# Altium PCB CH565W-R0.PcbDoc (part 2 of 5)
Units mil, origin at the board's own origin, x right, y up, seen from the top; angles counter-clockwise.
Board outline 3947.04 x 3947.04 mil, 4 copper layers (Top Layer, Layer 1, Layer 2, Bottom Layer), stack 23.756 mil thick; 204 components, 168 nets, 932 pads, 1005 vias.
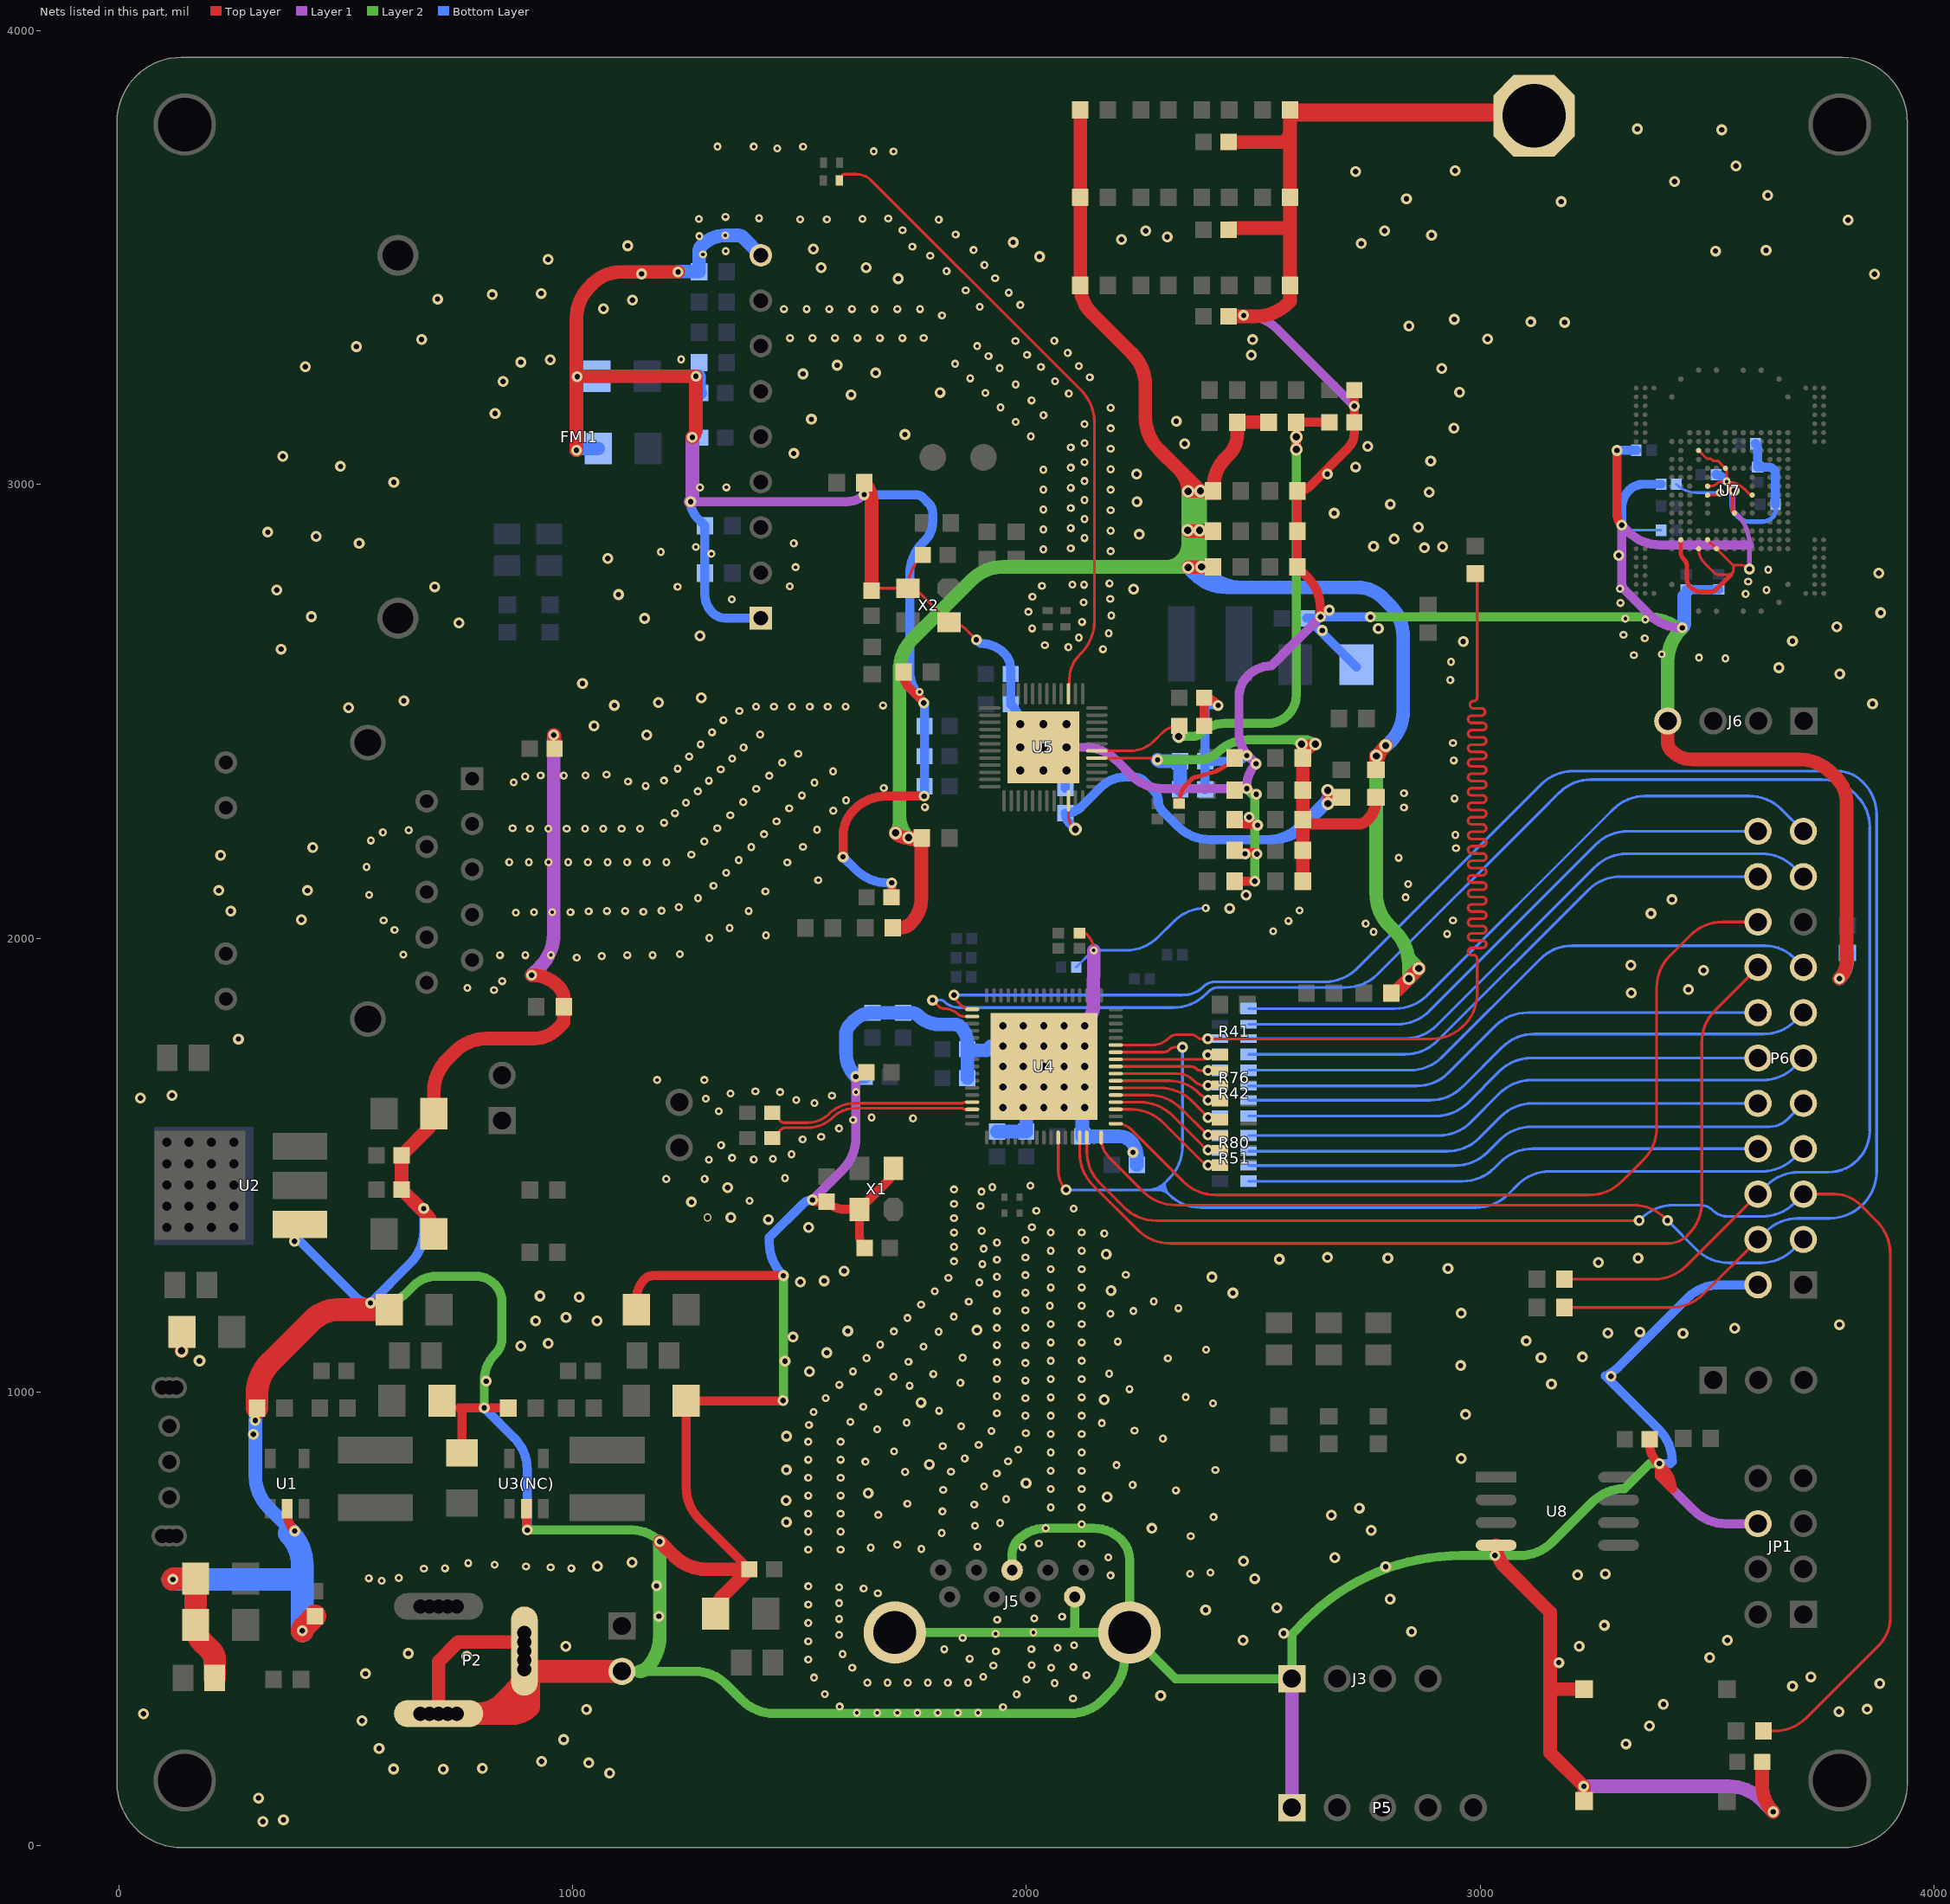
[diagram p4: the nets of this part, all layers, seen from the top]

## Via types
v1: diameter 17.72, hole 7.87, Top Layer to Bottom Layer, 556 vias
v2: diameter 24, hole 12, Top Layer to Bottom Layer, 366 vias
v3: diameter 28, hole 16, Top Layer to Bottom Layer, 63 vias
v4: diameter 17.72, hole 7.87, Top Layer to Bottom Layer, tented both sides, 8 vias
v5: diameter 24, hole 12, Top Layer to Bottom Layer, tented both sides, 5 vias
v6: diameter 26, hole 14, Top Layer to Bottom Layer, 2 vias
v7: diameter 19.68, hole 10, Top Layer to Bottom Layer, 1 vias
v8: diameter 20, hole 10, Top Layer to Bottom Layer, 1 vias
v9: diameter 28, hole 16, Top Layer to Bottom Layer, tented both sides, 1 vias
v10: diameter 32, hole 18, Top Layer to Bottom Layer, 1 vias
v11: diameter 17.72, hole 12, Top Layer to Bottom Layer, 1 vias

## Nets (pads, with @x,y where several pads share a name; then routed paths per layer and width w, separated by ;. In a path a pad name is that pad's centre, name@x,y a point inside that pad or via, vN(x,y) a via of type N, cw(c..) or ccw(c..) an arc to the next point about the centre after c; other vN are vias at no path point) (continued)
CMD_1: R41.6 R77.2 U4.29 | length 2954.6
  Top Layer w6: U4.29@2196.78,1764.37 2275.73,1764.37 ccw(c2275.73,1820.59) 2315.48,1780.83 ; 2315.5,1780.85 cw(c2331.46,1764.86) 2331.46,1787.45 2361.83,1787.45 cw(c2361.83,1765.31) 2377.49,1780.97 ccw(c2384.42,1787.9) 2384.42,1778.09 v2(2399.74,1778.09) 2893.6,1778.09 ccw(c2893.6,1878.09) 2993.6,1878.09 2993.6,1951.69 2993.6,1954.69 ccw(c2985.6,1954.69) 2985.6,1962.69 2981.6,1962.69 cw(c2981.6,1970.69) 2981.6,1978.69 3005.6,1978.69 ccw(c3005.6,1986.69) 3005.6,1994.69 2981.6,1994.69 cw(c2981.6,2002.69) 2981.6,2010.69 3005.6,2010.69 ccw(c3005.6,2018.69) 3005.6,2026.69 2981.6,2026.69 cw(c2981.6,2034.69) 2981.6,2042.69 3005.6,2042.69 ccw(c3005.6,2050.69) 3005.6,2058.69 2981.6,2058.69 cw(c2981.6,2066.69) 2981.6,2074.69 3005.6,2074.69 ccw(c3005.6,2082.69) 3005.6,2090.69 2981.6,2090.69 cw(c2981.6,2098.69) 2981.6,2106.69 3005.6,2106.69 ccw(c3005.6,2114.69) 3005.6,2122.69 2981.6,2122.69 cw(c2981.6,2130.69) 2981.6,2138.69 3005.6,2138.69 ccw(c3005.6,2146.69) 3005.6,2154.69 2981.6,2154.69 cw(c2981.6,2162.69) 2981.6,2170.69 3005.6,2170.69 ccw(c3005.6,2178.69) 3005.6,2186.69 2981.6,2186.69 cw(c2981.6,2194.69) 2981.6,2202.69 3005.6,2202.69 ccw(c3005.6,2210.69) 3005.6,2218.69 2981.6,2218.69 cw(c2981.6,2226.69) 2981.6,2234.69 3005.6,2234.69 ccw(c3005.6,2242.69) 3005.6,2250.69 2981.6,2250.69 cw(c2981.6,2258.69) 2981.6,2266.69 3005.6,2266.69 ccw(c3005.6,2274.69) 3005.6,2282.69 2981.6,2282.69 cw(c2981.6,2290.69) 2981.6,2298.69 3005.6,2298.69 ccw(c3005.6,2306.69) 3005.6,2314.69 2981.6,2314.69 cw(c2981.6,2322.69) 2981.6,2330.69 3005.6,2330.69 ccw(c3005.6,2338.69) 3005.6,2346.69 2981.6,2346.69 cw(c2981.6,2354.69) 2981.6,2362.69 3005.6,2362.69 ccw(c3005.6,2370.69) 3005.6,2378.69 2981.6,2378.69 cw(c2981.6,2386.69) 2981.6,2394.69 3005.6,2394.69 ccw(c3005.6,2402.69) 3005.6,2410.69 2981.6,2410.69 cw(c2981.6,2418.69) 2981.6,2426.69 3005.6,2426.69 ccw(c3005.6,2434.69) 3005.6,2442.69 2981.6,2442.69 cw(c2981.6,2450.69) 2981.6,2458.69 3005.6,2458.69 ccw(c3005.6,2466.69) 3005.6,2474.69 2981.6,2474.69 cw(c2981.6,2482.69) 2981.6,2490.69 3003,2490.69 ccw(c3003,2498.69) 3003,2506.69 2985.6,2506.69 cw(c2985.6,2514.69) 2985.6,2522.69 ccw(c2985.6,2530.69) 2993.6,2530.69 2993.6,2583.84 R77.2@2993.6,2803.67
  Bottom Layer w6: v2(2399.74,1778.09) cw(c2400.92,1776.92) 2400.92,1778.58 R41.6@2426.52,1778.58
CMD_2: R79.1 U7.R5 | length 130.2
  Top Layer w6: U7.R5@3501.47,2976.74 3515.72,2976.74 ccw(c3515.72,2995.22) v4(3528.79,2982.15)
  Bottom Layer w6: R79.1@3432.34,3000.83 ccw(c3477.44,3045.93) 3477.44,2982.15 v4(3528.79,2982.15)
DATA0: R41.5 R76.1 U4.27 | length 235.5
  Top Layer w6: U4.27@2196.78,1732.87 2390.04,1732.87 ccw(c2390.04,1742.61) v2(2399.78,1742.61) 2426.52,1742.61 R76.1@2426.52,1742.82
DATA1: R42.4 R76.2 U4.26 | length 205.7
  Top Layer w6: U4.26@2196.78,1717.12 2362.17,1717.12 cw(c2362.17,1699.04) 2374.96,1711.83 ccw(c2383.66,1720.52) 2383.66,1708.22 v2(2400.13,1708.22)
DATA2: R42.3 R76.3 U4.25 | length 210.8
  Top Layer w6: U4.25@2196.78,1701.37 2333.33,1701.37 cw(c2333.33,1653.71) 2367.03,1687.41 2367.21,1687.24 ccw(c2400.13,1720.16) v2@2400.13,1673.6
  other v2: 2400.13,1675.6
DATA3: R42.2 R76.4 U4.24 | length 241.4
  Top Layer w6: U4.24@2196.78,1685.63 2314.57,1685.63 cw(c2314.57,1592.62) 2380.34,1658.38 ccw(c2419.81,1697.85) 2419.81,1642.03 R76.4@2426.52,1642.03
  other v2: 2400.13,1642.97
DATA4: R42.1 R80.1 U4.23 | length 252.2
  Top Layer w6: U4.23@2196.78,1669.88 2294.3,1669.88 cw(c2294.3,1569.88) 2365.01,1640.59 2390.65,1614.95 ccw(c2426.52,1650.83) R80.1@2426.52,1600.1
  other v2: 2400.13,1604.35
DATA5: R51.4 R80.2 U4.22 | length 234.4
  Top Layer w6: U4.22@2196.78,1654.13 2269.88,1654.13 cw(c2269.88,1554.13) 2340.59,1624.84 v2@2399.07,1566.36
  other v2: 2400.13,1566.73
DATA6: R51.3 R80.3 U4.21 | length 267.4
  Top Layer w6: U4.21@2196.78,1638.38 2250.8,1638.38 cw(c2250.8,1538.38) 2321.51,1609.09 2387.57,1543.03 ccw(c2409.48,1564.94) 2409.48,1533.95 R80.3@2426.52,1533.95
  other v2: 2400.13,1533.1
DATA7: R51.2 R80.4 U4.20 | length 275.9
  Top Layer w6: U4.20@2196.78,1622.63 2230.76,1622.63 cw(c2230.76,1522.63) 2301.47,1593.34 2391.19,1503.62 ccw(c2399.07,1511.5) 2399.07,1500.36 ccw(c2401.61,1502.89) 2401.61,1499.31 R80.4@2426.52,1499.31
  other v2: 2400.13,1499.48
DP_CLK: P6.16 U4.14 | length 2123.8
  Top Layer w6.07: U4.14@2117.33,1560.34 2117.33,1526.1 ccw(c2217.33,1526.1) 2146.62,1455.39 2245.57,1356.45 ccw(c2316.28,1427.16) 2316.28,1327.16 3415.48,1327.16 ccw(c3415.48,1385.38) 3456.65,1344.21 3459.6,1347.16 ccw(c3389.29,1417.47) 3488.72,1417.47 3488.72,1770.43 cw(c3588.72,1770.43) 3518.01,1841.14 P6.16@3612.66,1935.79
DP_D0: P6.8 R51.8 | length 1144.2
  Bottom Layer w6.07: R51.8@2489.51,1464.19 2960.97,1464.19 ccw(c2960.97,1564.19) 3031.68,1493.48 3044.7,1506.5 cw(c3115.41,1435.79) 3115.41,1535.79 P6.8@3612.66,1535.79
DP_D1: P6.9 R51.7 | length 1268.8
  Bottom Layer w6.07: R51.7@2489.51,1498.84 2945.61,1498.84 ccw(c2945.61,1598.84) 3016.32,1528.13 3043.18,1554.99 cw(c3113.89,1484.28) 3113.89,1584.28 3637.83,1584.28 ccw(c3637.83,1640.61) 3677.65,1600.78 P6.9@3712.66,1635.79
DP_D2: P6.10 R51.6 | length 1158.2
  Bottom Layer w6.07: R51.6@2489.51,1530.33 2927.82,1530.33 ccw(c2927.82,1630.33) 2998.53,1559.62 3045.4,1606.5 cw(c3116.12,1535.79) 3116.12,1635.79 P6.10@3612.66,1635.79
DP_D3: P6.11 R51.5 | length 1281
  Bottom Layer w6.07: R51.5@2489.51,1564.98 2908.65,1564.98 ccw(c2908.65,1664.98) 2979.36,1594.27 3042.87,1657.78 cw(c3113.58,1587.06) 3113.58,1687.06 3622.52,1687.06 ccw(c3622.52,1787.06) 3693.23,1716.35 P6.11@3712.66,1735.79
DP_D4: P6.12 R42.8 | length 1167.5
  Bottom Layer w6.07: R42.8@2489.51,1608.03 2902.69,1608.03 ccw(c2902.69,1708.03) 2973.4,1637.32 3042.58,1706.5 cw(c3113.29,1635.79) 3113.29,1735.79 P6.12@3612.66,1735.79
DP_D5: P6.13 R42.7 | length 1290.4
  Bottom Layer w6.07: R42.7@2489.51,1642.68 2890.2,1642.68 ccw(c2890.2,1742.68) 2960.91,1671.96 3048.37,1759.43 cw(c3119.08,1688.71) 3119.08,1788.71 3625.78,1788.71 ccw(c3625.78,1884.82) 3693.74,1816.86 P6.13@3712.66,1835.79
DP_D6: P6.14 R42.6 | length 1181.5
  Bottom Layer w6.07: R42.6@2489.51,1674.17 2860.13,1674.17 ccw(c2860.13,1774.17) 2930.84,1703.46 3033.87,1806.5 cw(c3104.58,1735.79) 3104.58,1835.79 P6.14@3612.66,1835.79
DP_D7: P6.15 R42.5 | length 1344.2
  Bottom Layer w6.07: R42.5@2489.51,1708.82 2845.71,1708.82 ccw(c2845.71,1808.82) 2916.42,1738.11 3132.47,1954.16 cw(c3203.18,1883.45) 3203.18,1983.45 3628.41,1983.45 cw(c3628.41,1895.11) 3690.88,1957.57 P6.15@3712.66,1935.79
DP_D8: P6.20 R41.4 | length 1276.9
  Bottom Layer w6.07: R41.4@2489.51,1743.93 2834.65,1743.93 ccw(c2834.65,1843.93) 2905.36,1773.22 3238.64,2106.5 cw(c3309.35,2035.79) 3309.35,2135.79 P6.20@3612.66,2135.79
DP_D9: P6.19 R41.3 | length 1400
  Bottom Layer w6.07: R41.3@2489.51,1778.58 2833.7,1778.58 ccw(c2833.7,1878.58) 2904.41,1807.87 3253.47,2156.93 cw(c3324.18,2086.22) 3324.18,2186.22 3620.81,2186.22 cw(c3620.81,2086.22) 3691.52,2156.93 P6.19@3712.66,2135.79
DP_D10: P6.22 R41.2 | length 1290.9
  Bottom Layer w6.07: R41.2@2489.51,1810.08 2817.37,1810.08 ccw(c2817.37,1910.08) 2888.08,1839.37 3255.21,2206.5 cw(c3325.92,2135.79) 3325.92,2235.79 P6.22@3612.66,2235.79
DP_D11: P6.21 R41.1 | length 1436.5
  Bottom Layer w6.07: R41.1@2489.51,1844.72 2812.59,1844.72 ccw(c2812.59,1944.72) 2883.3,1874.01 3282.19,2272.91 3293.33,2284.04 cw(c3364.04,2213.33) 3364.04,2313.33 3593.7,2313.33 cw(c3593.7,2213.33) 3664.41,2284.04 P6.21@3712.66,2235.79
DP_HREF: P6.5 R27.1 U4.15 | length 3176.3
  Top Layer w6.07: U4.15@2133.08,1560.34 2133.08,1529.93 ccw(c2233.08,1529.93) 2162.37,1459.21 2214.95,1406.63 ccw(c2285.66,1477.34) 2285.66,1377.34 v2(3350.77,1377.34) ; R27.1@3624.9,252.09 3648.7,252.09 ccw(c3648.7,352.09) 3719.41,281.37 3878.66,440.63 ccw(c3816.73,502.56) 3904.31,502.56 3904.31,1304.48 ccw(c3804.31,1304.48) 3875.02,1375.19 3837.65,1412.57 ccw(c3781.59,1356.5) 3781.59,1435.79 P6.5@3718.64,1435.79
  Bottom Layer w6.07: v2(3350.77,1377.34) 3355.64,1382.21 cw(c3426.35,1311.5) 3426.35,1411.5 3485.15,1411.5 cw(c3485.15,1372) 3513.08,1399.93 ccw(c3545.42,1432.27) 3545.42,1386.53 3621.99,1386.53 ccw(c3621.99,1486.53) 3692.7,1415.82 P6.5@3712.66,1435.79
DP_PWDN: P6.18 U4.18 | length 1936.4
  Top Layer w6.07: U4.18@2196.78,1591.14 2199.66,1591.14 cw(c2199.66,1546.52) 2231.21,1578.07 2346.1,1463.18 ccw(c2416.81,1533.9) 2416.81,1433.9 3241.27,1433.9 ccw(c3241.27,1533.9) 3311.99,1463.18 3360.01,1511.21 ccw(c3289.3,1581.92) 3389.3,1581.92 3389.3,1890.85 cw(c3489.3,1890.85) 3418.59,1961.56 3463.53,2006.5 cw(c3534.24,1935.79) 3534.24,2035.79 P6.18@3612.66,2035.79
DP_RESET: P6.7 U4.11 U4.28 | length 2382.8
  Top Layer w6: U4.11@2070.09,1560.34 2070.09,1486.96 ccw(c2129.33,1486.96) v2(2087.44,1445.06) ; U4.28@2196.78,1748.62 2301.85,1748.62 ccw(c2301.85,1767.37) 2315.11,1754.11 cw(c2328.37,1740.85) 2328.37,1759.6 v2(2343.86,1759.6)
  Bottom Layer w6: v2(2087.44,1445.06) 2268.26,1445.06 ; 2295.79,1446.3 2299.31,1449.83 ; 2303.99,1453.09 ccw(c2303.99,1449.66) 2301.57,1452.08 2299.31,1449.83 ; 2313.86,1435.28 ccw(c2384.57,1505.99) 2384.57,1405.99 2991.19,1405.99 ccw(c2991.19,1505.99) 3061.9,1435.28 3083.28,1456.66 cw(c3153.99,1385.95) 3153.99,1485.95 3621.4,1485.95 ccw(c3621.4,1585.95) 3692.11,1515.24 P6.7@3712.66,1535.79 ; v2(2343.86,1759.6) 2343.86,1540.73 cw(c2243.86,1540.73) 2314.57,1470.02 2304.72,1460.17 ; 2268.26,1445.06 ccw(c2268.26,1496.63) 2295.99,1453.15 ; 2268.26,1445.06 2290.24,1445.06 ; 2290.24,1445.06 cw(c2291.75,1445.06) 2290.68,1446.13 2296.85,1452.29 ; 2290.24,1445.06 cw(c2290.24,1411.67) 2313.85,1435.29 ; 2295.99,1453.15 ccw(c2268.26,1496.63) 2304.72,1460.17 ; 2295.99,1453.15 2296.85,1452.29 ; 2296.85,1452.29 2304.72,1460.17 ; 2296.85,1452.29 2299.31,1449.83 ; 2299.31,1449.83 2313.85,1435.29 ; 2304.72,1460.17 2304.72,1457.34 ccw(c2335.91,1457.34) 2313.85,1435.29
DP_SCL: P6.4 R65.1 U4.52 | length 3946.9
  Top Layer w6.07: v2@1834.14,1873.51 1853.32,1854.33 ccw(c1880.41,1881.43) U4.52@1880.41,1843.11 ; R65.1@3184.61,1185.93 3421.39,1185.93 ccw(c3421.39,1285.93) 3492.1,1215.22 P6.4@3612.66,1335.79
  Bottom Layer w6.07: v2(1840.14,1874.51) 2344.63,1874.51 ccw(c2344.63,1939.35) 2362.64,1877.06 ccw(c2344.63,1939.35) 2376.51,1882.88 ccw(c2344.63,1939.35) 2390.48,1893.5 cw(c2415.41,1868.57) 2415.41,1903.82 2657.99,1903.82 ccw(c2657.99,2003.82) 2728.7,1933.11 3090.62,2295.03 3134.64,2339.06 cw(c3205.35,2268.35) 3205.35,2368.35 3787.69,2368.35 cw(c3787.69,2291.49) 3842.04,2345.84 3844.77,2343.11 cw(c3774.06,2272.4) 3874.06,2272.4 3874.06,2228.03 3874.06,1486.1 cw(c3770.2,1486.1) 3770.2,1382.24 3700.54,1382.24 ccw(c3700.54,1282.24) 3629.83,1352.96 P6.4@3612.66,1335.79
DP_SDA: P6.6 R64.1 U4.53 | length 3909.3
  Top Layer w6.07: v2(1792.99,1863.44) 1806.45,1849.97 ccw(c1819.12,1862.64) 1819.12,1844.73 cw(c1819.12,1801.49) 1849.69,1832.07 ccw(c1861.05,1843.43) 1861.05,1827.36 U4.53@1880.41,1827.36 ; R64.1@3182.86,1248.07 3383.52,1248.07 ccw(c3383.52,1348.07) 3454.23,1277.36 P6.6@3612.66,1435.79
  Bottom Layer w6.07: v2(1792.99,1863.44) 1811.08,1863.44 cw(c1811.08,1852.38) 1818.89,1860.2 ccw(c1850.61,1891.92) 1850.61,1847.06 2324.48,1847.06 ccw(c2324.48,1947.06) 2395.19,1876.35 2400.98,1882.14 cw(c2423.81,1859.31) 2423.81,1891.6 2703.84,1891.6 ccw(c2703.84,1991.6) 2774.55,1920.88 3132.01,2278.35 3174.22,2320.55 cw(c3244.93,2249.84) 3244.93,2349.84 3753.73,2349.84 cw(c3753.73,2249.84) 3824.44,2320.55 3829.84,2315.15 cw(c3759.13,2244.44) 3859.13,2244.44 3859.13,2207.64 3859.13,1575.61 cw(c3767.56,1575.61) 3767.56,1484.05 3702.34,1484.05 ccw(c3702.34,1384.05) 3631.63,1454.76 P6.6@3612.66,1435.79
DP_SYNC: P6.3 U4.17 | length 1679.2
  Top Layer w6.07: U4.17@2164.58,1560.34 ccw(c2227.67,1560.34) 2183.06,1515.73 2257.9,1440.89 ccw(c2328.61,1511.6) 2328.61,1411.6 3337.44,1411.6 cw(c3337.44,1311.6) 3408.15,1382.31 v2(3413.12,1377.34)
  Bottom Layer w6.07: v2(3413.12,1377.34) 3476.94,1313.52 ccw(c3547.65,1384.23) 3547.65,1284.23 3619.68,1284.23 ccw(c3619.68,1384.23) 3690.39,1313.52 P6.3@3712.66,1335.79
DVDD10: C52.2 R56.2 U5.22 | length 1201.1
  Top Layer w6: U5.22@2092.35,2302.68 2092.35,2272.72 ccw(c2138.17,2272.72) v3@2105.77,2240.32
  Top Layer w20: v3(2663.95,2325.72) 2663.95,2297.9 ccw(c2665.54,2297.9) v3(2664.42,2296.78) ; 2665.42,2310.78 2665.59,2310.61 R56.2@2694.06,2310.61
  Bottom Layer w20: v3(2107.77,2240.32) 2094.9,2253.2 cw(c2117.29,2275.59) C52.2@2085.63,2275.59 ccw(c2085.63,2327.11) 2122.06,2290.68 2164.91,2333.53 cw(c2217.16,2281.29) 2217.16,2355.17 2237.13,2355.17 cw(c2237.13,2322.58) 2260.18,2345.63 2282.04,2323.77 cw(c2263.77,2305.51) 2289.6,2305.51 ccw(c2325.58,2305.51) 2300.12,2280.08 2333.6,2246.61 ccw(c2404.31,2317.32) 2404.31,2217.32 2530.53,2217.32 ; 2530.53,2217.32 ccw(c2530.53,2317.32) 2601.24,2246.61 ; 2530.53,2217.32 ccw(c2530.53,2317.32) 2601.24,2246.61 ; 2530.53,2217.32 2543.53,2217.32 ccw(c2543.53,2317.32) 2614.24,2246.61 v3(2664.42,2296.78) ; 2601.24,2246.61 v3@2652.36,2297.72 ; v3@2652.36,2297.72 ccw(c2624.36,2325.72) v3@2663.95,2325.72 ; v3@2652.36,2297.72 v3@2663.95,2309.32 ; v3@2663.95,2309.32 v3(2663.95,2325.72) ; v3@2663.95,2309.32 2663.95,2297.9 ccw(c2665.54,2297.9) v3(2664.42,2296.78) ; v3@2663.95,2309.32 v3@2664.42,2309.78 ; v3@2663.95,2325.72 cw(c2662.83,2324.6) 2664.42,2324.6 v3@2664.42,2309.78 ; v3(2664.42,2296.78) v3@2664.42,2309.78
DVDD33: R17.2 R18.1 R28.1 R35.2 R37.1 R39.1 R43.2 R53.1 R57.1 R63.2 R66.1 R70.1 | length 5174
  Top Layer w30: R43.2@1705.4,2023.17 1721.35,2023.17 ccw(c1721.35,2057.54) 1745.65,2033.23 ccw(c1691.21,2087.68) 1768.21,2087.68 1768.21,2217.84 1749.32,2217.84 cw(c1749.32,2231.33) v3@1740.88,2220.81 ; v3(1711.3,2232) ccw(c1738.32,2259.02) 1738.32,2220.81 v3@1740.88,2220.81 ; v3(1739.79,2221.79) ccw(c1749.32,2231.33) v3@1740.88,2220.81 ; R53.1@1769.44,2220.81 v3@1740.88,2220.81 ; R66.1@2118.6,3823.63 R57.1@2118.6,3633.33 R70.1@2118.6,3439.1 ccw(c2205.54,3439.1) 2144.06,3377.62 2232.9,3288.78 cw(c2162.19,3218.07) 2262.19,3218.07 2262.19,3148.47 ccw(c2362.19,3148.47) 2291.48,3077.76 2336.65,3032.6 ; v3(2356.23,2817.13) cw(c2359.28,2814.07) 2359.28,2818.39 v3@2386.09,2818.39 ; v3@2356.23,2897.13 R37.1@2411.47,2897.13 ccw(c2406.24,2891.9) 2406.24,2899.3 v3(2381.77,2899.3) ; v3(2385.96,2818.51) v3@2386.09,2818.39 ; R28.1@2411.47,2818.39 v3@2386.09,2818.39 ; R18.1@2533.95,3137.48 R17.2@2464.53,3137.48 2464.53,3108.65 cw(c2405.98,3108.65) 2447.39,3067.26 2440.76,3060.63 ccw(c2511.47,2989.92) 2411.47,2989.92 R39.1@2411.47,2985.87 v3@2383.72,2985.87 ; R63.2@2770.33,2371.24 R63.2@2770.33,2372.53 ; v3(2771.11,2401.8) ccw(c2773.01,2399.9) 2770.33,2399.9 R63.2@2770.33,2372.53 ; v3(2791.87,2424.54) ccw(c2843.89,2372.53) R63.2@2770.33,2372.53 ; v3(2842.78,1910.56) 2816.38,1884.17 cw(c2804.2,1896.36) R35.2@2804.2,1879.13 ccw(c2804.2,1895.41) 2815.71,1883.9 v3(2865.11,1933.29) ; 2336.65,3032.6 cw(c2289.38,2985.32) v3(2356.23,2985.32) cw(c2357.55,2984.01) 2357.55,2985.87 v3@2383.38,2985.87 ; 2336.65,3032.6 v3@2383.38,2985.87 ; v3@2383.38,2985.87 v3(2383.55,2985.7) v3@2383.72,2985.87 ; v3@2383.38,2985.87 v3@2383.72,2985.87
  Layer 2 w30: v3(2385.96,2818.51) v3@2382.96,2818.51 ; v3(2771.11,2401.8) 2771.11,2097.77 ccw(c2871.11,2097.77) 2800.4,2027.06 2813.49,2013.97 cw(c2742.78,1943.26) 2841.52,1959.04 ; 2839.87,1967.17 ccw(c2860.75,1967.17) 2841.52,1959.04 ; 1720.15,2269.2 ccw(c1787.2,2269.2) v3@1739.74,2221.84 ; 1720.15,2269.2 1720.15,2589.43 cw(c1820.15,2589.43) 1749.44,2660.14 1878.52,2789.22 cw(c1949.23,2718.51) 1949.23,2818.51 2306.75,2818.51 ; 1720.15,2269.2 1720.15,2253.37 cw(c1689.93,2253.37) v3(1711.3,2232) 1715.14,2232 cw(c1715.14,2197.14) v3@1739.74,2221.84 ; v3@1739.74,2221.84 ccw(c1787.2,2269.2) v3(1739.79,2221.79) ccw(c1715.14,2197.14) v3@1739.74,2221.84 ; 2306.75,2818.51 ccw(c2306.75,2868) 2356.23,2868 ; 2306.75,2818.51 v3@2356.23,2818.51 ; v3@2356.23,2818.51 2356.23,2868 ; v3@2356.23,2818.51 v3@2382.96,2818.51 ; 2356.23,2868 v3(2356.23,2985.32) 2377.51,2985.32 cw(c2377.51,2979.87) 2382.96,2979.87 v3@2382.96,2818.51 ; 2841.52,1959.04 cw(c2742.78,1943.26) 2842.78,1943.26 v3(2842.78,1910.56) 2865.11,1932.9 v3(2865.11,1933.29) 2845.99,1952.41 cw(c2860.75,1967.17) 2841.52,1959.04
  Bottom Layer w30: v3(2771.11,2401.8) 2802.4,2433.09 ccw(c2734.82,2500.67) 2830.39,2500.67 2830.39,2664.08 ccw(c2730.39,2664.08) 2801.1,2734.79 2786.27,2749.63 ccw(c2728.62,2691.99) 2728.62,2773.51 2472.39,2773.51 ; 2472.39,2773.51 cw(c2472.39,2873.51) 2401.68,2802.8 v3(2385.96,2818.51) 2359.58,2818.51 ccw(c2359.58,2813.78) v3(2356.23,2817.13) 2370.56,2802.8 ccw(c2441.27,2873.51) 2441.27,2773.51 2472.39,2773.51
  other v3: 2355.23,2899.13
DVDDLDO: C24.2 C25.2 R18.2 U5.30 | length 1235.8
  Top Layer w6: U5.30@2155.35,2412.92 2228.4,2412.92 ccw(c2228.4,2487.44) 2281.09,2434.75 2298.54,2452.2 cw(c2336.58,2414.16) C24.2@2336.58,2467.96
  Top Layer w20: v3(2594.92,3104.97) 2594.58,3105.31 R18.2@2594.58,3137.48 ; v3(2594.98,3077.36) 2594.98,3136.53 ccw(c2593.63,3136.53) R18.2@2594.58,3137.48 ; C25.2@2667.62,3137.48 R18.2@2594.58,3137.48
  Layer 2 w20: v3(2335.71,2444.71) 2368.06,2444.71 ccw(c2368.06,2463.26) 2381.18,2450.14 cw(c2437.35,2393.97) 2437.35,2473.41 2531.74,2473.41 ccw(c2531.74,2536.6) 2594.92,2536.6 v3(2594.92,3104.97)
DVDDREG: C55.2 C56.2 R30.1 R32.1 R45.1 R47.1 R49.1 R63.1 U5.29 | length 1190.3
  Top Layer w6: U5.29@2155.35,2397.17 2279.37,2397.17 cw(c2279.37,2383.51) v2(2289.04,2393.17)
  Top Layer w20: v3(2606.08,2427.9) 2606.24,2428.05 v3(2636.78,2428.05) 2611.27,2402.54 ccw(c2616.22,2397.59) R30.1@2609.22,2397.59
  Top Layer w25: R45.1@2609.22,2251.58 2729.73,2251.58 ccw(c2729.73,2283.39) 2752.23,2260.89 ccw(c2708.54,2304.59) 2770.33,2304.59 R63.1@2770.33,2310.61
  Top Layer w30: R49.1@2609.22,2125.57 2609.22,2251.58 R45.1@2609.22,2261.58 R32.1@2609.22,2326.58 2609.22,2377.59
  Layer 2 w20: v2(2289.04,2393.17) 2381.38,2393.17 ccw(c2381.38,2450.28) 2421.77,2409.9 cw(c2488.31,2343.36) 2488.31,2437.46 2582.99,2437.46 ; 2582.99,2437.46 cw(c2582.99,2404.81) v3(2606.08,2427.9) 2606.24,2428.05 v3(2636.78,2428.05) ccw(c2614.07,2405.34) 2614.07,2437.46 2582.99,2437.46
  Bottom Layer w30: v2(2289.04,2393.17) ccw(c2296.38,2400.51) 2296.38,2390.13 C55.2@2338.75,2390.13 C56.2@2338.75,2328.02
EX_n: C73.1 U4.65 | length 461.6
  Top Layer w6.07: C73.1@1439.59,1615.2 1458.68,1596.12 ccw(c1465.75,1603.2) 1465.75,1593.19 1517.84,1593.19 ccw(c1517.84,1659.82) 1564.96,1612.71 1565.06,1612.81 cw(c1621.14,1556.73) 1621.14,1636.04 1859.25,1636.04 cw(c1864.9,1630.39) 1864.9,1638.38 U4.65@1880.41,1638.38
EX_p: C74.1 U4.66 | length 461.8
  Top Layer w6.07: C74.1@1439.59,1559.12 1458.59,1578.12 cw(c1468.25,1568.47) 1468.25,1582.12 1517.88,1582.12 ccw(c1517.88,1659.72) 1572.75,1604.85 ; 1572.78,1604.88 cw(c1621.29,1556.37) 1621.29,1624.97 1859.25,1624.97 ccw(c1864.9,1630.62) 1864.9,1622.63 U4.66@1880.41,1622.63
GND: C1.1 C2.1 C3.1 C5.1 C6.1 C7.1 C8.1 C9.1 C10.1 C11.1 C13.1 C14.1 C15.1 C16.1 C17.1 C18.1 C19.2 C20.2 C21.2 C22.2 C23.2 C24.1 C25.1 C26.1 C27.2 C32.2 C33.2 C34.2 C35.1 C36.1 C37.1 C38.1 C39.1 C40.2 C41.1 C42.1 C43.1 C44.1 C45.1 C46.1 C47.2 C48.1 C49.1 C50.1 C51.1 C52.1 C53.2 C54.2 C55.1 C56.1 C57.1 C58.2 C59.1 C60.2 C61.2 C62.2 C63.2 C64.2 C65.1 C66.2 C67.2 C68.2 C69.2 C70.2 C75.1 D1.2 FMI1.1 FMI1.9 J3.1 J5.0 J5.4 J5.7 J6.4 JP1.6 P2.2 P2.3 P4.2 P5.1 P6.2 pad.@3119.01,3813.24 R3.1 R5.1 R6.2 R7.2 R14.2 R19.1 R23.1 R24.1 R29.2 R31.2 R33.2 R38.2 R40.2 R46.2 R48.2 R50.2 R55.2 R61.2 R69.2 R73.2 R79.2 R88.1 S1.2 S2.1 U1.2 U2.1 U3(NC).2 U4.0 U5.49 U7.AA4 U7.AA6 U7.K4 U7.M7 U7.P5 U7.R10 U7.U8 U7.Y2 U7.Y5 U8.4 X1.2 X1.4 X2.2 X2.4 | length 30073.7
  Top Layer w6: C57.1@1658.43,2766.06 cw(c1671.24,2753.25) 1671.24,2771.36 X2.2@1738.73,2771.36 ; C59.1@1767.5,2840.83 ccw(c1837.01,2771.36) X2.2@1738.73,2771.36 ; C59.1@1767.52,2840.85 C59.1@1771.58,2844.91 ; v2(1889.54,2657.88) 1866.12,2681.3 ccw(c1829.29,2644.47) X2.4@1829.29,2696.56 1765.62,2760.23 ccw(c1738.73,2733.34) X2.2@1738.73,2771.36 ; C27.2@2120.59,2017.59 2128.84,2012.55 2134.13,2007.26 cw(c2099.99,1973.12) v1(2148.27,1973.12) ; U7.AA4@3481.78,2858.63 ccw(c3527.17,2858.63) 3495.07,2826.53 3515.89,2805.72 ccw(c3526.21,2816.06) 3526.21,2801.45 3553.28,2801.45 ccw(c3539.21,2815.52) 3559.1,2815.52 3559.1,2818.04 ccw(c3552.73,2818.04) 3557.24,2822.54 ; U7.K4@3481.78,3075.16 3499.87,3057.07 3508.54,3057.07 3513.02,3052.59 3524.04,3052.59 U7.M7@3540.84,3035.79 cw(c3533.73,3028.68) 3543.78,3028.68 v4(3543.78,3006.83) ; U7.Y5@3501.47,2878.31 U7.AA6@3521.15,2858.63 3557.24,2822.54 ; U7.P5@3501.47,2996.42 3507.48,2996.42 ccw(c3507.48,3018.47) 3523.07,3002.88 cw(c3532.61,2993.34) 3532.61,3006.83 3540.67,3006.83 cw(c3540.67,2945.26) 3543.86,3006.75 cw(c3540.67,2945.26) 3584.2,2988.8 3593.7,2979.3 ccw(c3599.89,2985.49) U7.R10@3599.89,2976.74 ; v2(3593.91,2813.9) ccw(c3573.06,2793.06) 3573.06,2822.54 3557.24,2822.54
  Top Layer w10: C26.1@2336.45,2296.65 cw(c2399.14,2296.65) 2354.81,2340.98 2365.68,2351.84 cw(c2372.75,2344.77) 2369.98,2354.38 2419.52,2368.69 ccw(c2416.74,2378.3) 2421.68,2369.6 2444.69,2382.73 ccw(c2439.74,2391.42) 2446.81,2384.35 2457.39,2394.93 R31.2@2457.39,2395.91 ; R31.2@2459.06,2397.59 cw(c2471.6,2385.05) 2471.6,2402.78 v2(2485.8,2402.78) ; U7.Y2@3442.41,2878.31 3442.41,2851.32 ccw(c3464.41,2851.32) 3448.85,2835.77 cw(c3431.73,2818.65) 3455.95,2818.65 3455.95,2791.65 ccw(c3480.87,2791.65) 3463.25,2774.03 ccw(c3487.92,2798.7) 3487.92,2763.8 3508.09,2763.8 ccw(c3508.09,2782) 3520.96,2769.13 3553.28,2801.45 ; v4(3543.78,3006.83) cw(c3514.09,2977.14) 3543.86,3006.75 cw(c3514.09,2977.14) 3556.08,2977.14 3556.08,2948.09 ccw(c3571.25,2948.09) U7.U8@3560.52,2937.37
  Top Layer w20: U1.2@370.27,742.39 370.27,733 ccw(c426.68,733) v2(386.79,693.11) ; v2(553.86,1195.84) ccw(c589.51,1231.5) C2.1@589.51,1181.08 ; C11.1@755.6,865.01 755.6,950.24 ccw(c736.01,950.24) 749.86,964.09 R5.1@857.74,964.09 ; 897.4,742.39 897.4,700.36 ccw(c904.78,700.36) v2(899.56,695.14) ; C14.1@1139.85,1181.08 1139.85,1202.93 cw(c1204.83,1202.93) 1158.88,1248.88 cw(c1176.01,1231.75) 1176.01,1255.98 v2(1463.99,1255.98) ; C66.2@1389.06,608.6 1279.13,718.52 cw(c1349.85,789.23) 1249.85,789.23 C13.1@1249.85,980.05 1461.33,980.05 ccw(c1461.33,982.7) v2(1463.2,980.83) ; v2(1528.1,1422.92) ccw(c1537.12,1431.95) 1537.12,1419.18 C47.2@1558.97,1419.18 ccw(c1600.13,1460.34) 1600.13,1402.13 X1.4@1631.8,1402.13 ; v2(1595.59,2179.32) 1595.59,2224.95 cw(c1677.79,2224.95) 1619.67,2283.07 1620.44,2283.84 cw(c1691.15,2213.13) 1691.15,2313.13 v2(1774.36,2313.13) ; v2(1642.15,2977.88) 1642.47,2978.2 R19.1@1642.47,3004.25 ; C48.1@1643.26,1317 cw(c1670.95,1344.68) 1631.8,1344.68 X1.4@1631.8,1402.13 ; C39.1@1702.57,2090.31 1702.57,2121.89 v2(1702.67,2121.99) ; X1.2@1706.6,1492.68 cw(c1668.58,1492.68) 1695.46,1465.8 X1.4@1631.8,1402.13 ; R14.2@1728.92,2582.75 ccw(c1772.19,2582.75) 1741.59,2552.15 v2@1775.32,2518.42 ; C24.1@2391.58,2467.96 C17.1@2391.58,2530.02 cw(c2391.58,2495.97) 2415.66,2520.04 v2(2422.49,2513.21) ; 2479.06,2125.57 2503.11,2125.57 v2(2503.42,2125.25) ; v2@2479.06,2188.57 2500.84,2188.57 cw(c2500.84,2178.32) v2(2508.08,2185.57) ; 2479.06,2251.58 v2@2501.61,2251.58 ; v2(2648.19,2708.6) 2648.19,2726 ccw(c2548.19,2726) 2618.9,2796.71 R29.2@2597.22,2818.39 R38.2@2597.22,2897.13 R40.2@2597.22,2985.87 ccw(c2597.22,3026.61) 2626.03,2997.8 2709.17,3080.95 ccw(c2676.71,3113.41) 2722.62,3113.41 C25.1@2722.62,3137.48 v2(2722.62,3172.88) C18.1@2722.62,3208.28 ; v2(3032.56,639.01) ccw(c3025.78,645.78) 3035.36,645.78 U8.4@3035.36,661.58 ; v2(3301.61,3075.17) 3301.61,2935.84 ccw(c3337.39,2935.84) v2(3312.09,2910.53) ; C65.1@3374.03,895.12 3374.03,884.16 ccw(c3431.03,884.16) 3390.73,843.86 v2@3395.43,839.16 ; v2(3395.43,841.75) v2@3395.43,839.16 ; v2@3395.43,839.16 3405.92,828.67 cw(c3363.46,786.21) 3423.5,786.21 3395.43,814.29 v2@3395.43,839.16
  Top Layer w30: v3(137.58,1090.09) ccw(c135.8,1091.87) 138.32,1091.87 C3.1@138.32,1131.85 ; v2@667.57,1400.4 C8.1@622.28,1445.69 C6.1@622.28,1521.29 678.78,1577.78 ccw(c643.24,1613.32) C5.1@693.5,1613.32 693.5,1661.73 cw(c793.5,1661.73) 722.79,1732.44 739.92,1749.57 cw(c810.63,1678.86) 810.63,1778.86 914.52,1778.86 ccw(c914.52,1850.66) 965.29,1799.89 979.93,1814.53 R55.2@979.93,1848.76 979.93,1866.61 ccw(c943.04,1866.61) 969.13,1892.7 967.24,1894.58 ccw(c909.29,1836.63) v2(909.29,1918.59) ; v2@674.9,1393.07 cw(c630.01,1348.18) C7.1@693.5,1348.18 ; P2.2@704.07,290.45 703.92,290.61 703.92,405.06 747.1,448.25 P2.3@893.05,448.25 ; v2(957.83,2448.12) cw(c953.27,2443.56) 959.72,2443.56 C40.2@959.72,2418.14 ; v2(1008.01,3075.71) 1008.01,3365.86 cw(c1108.01,3365.86) 1037.3,3436.57 1043.9,3443.17 cw(c1105.36,3381.71) 1105.36,3468.63 v2(1231.99,3468.63) ; v2(1009.6,3237.62) cw(c1012.2,3235.03) 1012.2,3238.7 v2(1271.35,3238.7) 1271.35,3123.37 cw(c1244.23,3123.37) v2(1263.41,3104.19) ; v2(1191.67,669.83) 1223.61,637.89 ccw(c1294.32,708.6) 1294.32,608.6 C66.2@1389.06,608.6 1331.55,551.1 ccw(c1371.68,510.97) C70.2@1314.93,510.97 ; R19.1@1642.47,3004.25 cw(c1603.92,2965.7) 1658.43,2965.7 C57.1@1658.43,2766.06 ; C58.2@2445.39,3370.91 2506.13,3370.91 ccw(c2506.13,3470.91) 2576.84,3400.2 2581.05,3404.42 R73.2@2581.05,3439.1 2581.05,3565.6 ; C53.2@2445.39,3562.09 cw(c2453.86,3553.62) 2453.86,3565.6 2581.05,3565.6 ; C54.2@2450.39,3755.1 2560.43,3755.1 ccw(c2560.43,3771.04) 2571.7,3759.77 ccw(c2549.13,3782.34) 2581.05,3782.34 ; R69.2@2595.48,3820.24 cw(c2595.48,3840.64) R69.2@2581.05,3826.22 2581.05,3782.34 ; U8.4@3035.36,661.58 ccw(c3104.05,661.58) 3055.48,613.01 3154.59,513.9 3154.59,344.71 ; S1.2@3229.3,97.75 3229.3,128.81 ccw(c3227.27,128.81) v2(3228.7,130.24) 3154.59,204.36 3154.59,344.71 ; S2.1@3229.3,344.38 3154.92,344.38 3154.59,344.71 ; J6.4@3413.66,2478.72 3413.66,2433.31 ccw(c3442.52,2433.31) 3422.11,2412.91 ccw(c3467.87,2458.67) 3467.87,2393.96 3703.62,2393.96 cw(c3703.62,2293.96) 3774.33,2364.67 3785.13,2353.87 cw(c3730.58,2299.31) 3807.73,2299.31 3807.73,1948.61 cw(c3754.06,1948.61) v2(3792.01,1910.66) ; C33.2@3622.1,184.19 3622.1,131.62 ccw(c3703.82,131.62) v2(3646.03,73.83) ; 2581.05,3565.6 R61.2@2581.05,3633.33 2581.05,3782.34
  Top Layer w39.37: R69.2@2595.48,3820.24 pad.@3119.01,3820.24
  Top Layer w50: v2(118.37,586.36) cw(c122.65,582.08) 122.65,588.13 C9.1@168.31,588.13 C75.1@168.31,486.14 ccw(c224.61,486.14) 184.8,446.32 202.08,429.04 cw(c181.93,408.9) 210.43,408.9 D1.2@210.43,369.48 ; R3.1@303.6,964.09 303.6,993.9 cw(c403.6,993.9) 332.89,1064.61 425.24,1156.97 cw(c483.44,1098.77) 483.44,1181.08 C2.1@589.51,1181.08 ; v2(403.49,473.09) cw(c413.43,473.09) 406.39,480.1 C10.1@431.73,505.44 ; P2.2@704.07,290.45 P2.2@724.07,290.45 P2.2@744.07,290.45 P2.2@795.03,290.45 ; P2.3@893.05,408.25 cw(c870.71,385.91) 902.3,385.91 P2.3@902.3,383.74 ; P4.2@1108.22,383.63 904.2,383.63 cw(c904.2,399.4) P2.3@902.3,383.74 ; P2.2@795.03,290.45 ccw(c795.03,359.66) 843.97,310.72 872.93,339.68 ccw(c824.36,388.25) P2.3@893.05,388.25 ccw(c904.2,399.4) P2.3@902.3,383.74 ; P2.2@795.03,290.45 865.63,290.45 ccw(c865.63,342.31) 902.3,305.64 P2.3@902.3,383.74
  Layer 1 w10: 3558.4,2942.43 cw(c3560.64,2944.65) 3557.49,2944.65 3557.49,2981.47 cw(c3565.6,2981.47) v2(3559.86,2987.21) ; 3558.41,2942.42 3573.55,2927.28 cw(c3493.91,2866.81) 3593.91,2866.81 v2(3593.91,2813.9)
  Layer 1 w20: v2(1259.73,2962.37) 1604.7,2962.37 ccw(c1604.7,3015.33) v2(1642.15,2977.88) ; v2(1528.1,1422.92) 1594.55,1489.37 ccw(c1523.84,1560.08) 1623.84,1560.08 v2(1623.84,1694.8) ; U5.49@2088.42,2420.79 2127.85,2420.79 cw(c2127.85,2320.79) 2198.56,2391.5 2230.95,2359.12 ccw(c2301.66,2429.83) 2301.66,2329.83 v2(2485.62,2329.83) 2485.62,2334.78 cw(c2555.98,2334.78) v2(2506.23,2384.53) v2@2489.52,2401.24 ; v2(2478.89,3373.09) 2480.99,3373.09 cw(c2480.99,3273.09) 2551.71,3343.8 v2(2722.62,3172.88) ; v2(2485.8,2402.78) cw(c2485.8,2397.52) 2489.5,2401.26 cw(c2540.33,2452.06) 2468.46,2452.06 2468.46,2532.51 cw(c2531.66,2532.51) 2486.97,2577.19 2488.82,2579.04 cw(c2539.71,2528.15) 2539.71,2600.12 v2(2648.19,2708.6) ; v2(3395.43,841.75) 3395.43,814.29 3471.2,738.52 ccw(c3541.91,809.23) 3541.91,709.23 JP1.6@3612.66,709.23 ; v2(3446.04,2684.26) 3443.71,2684.26 cw(c3443.71,2784.26) 3373,2713.55 3318.98,2767.57 cw(c3335.61,2784.2) 3312.09,2784.2 v2(3312.09,2910.53) 3326.52,2896.1 ccw(c3397.24,2966.81) 3397.24,2866.81 3593.91,2866.81
  Layer 1 w30: v2(909.29,1918.59) 928.54,1937.84 ccw(c857.83,2008.55) 957.83,2008.55 v2(957.83,2448.12) ; v2(1259.73,2962.37) ccw(c1250.87,2971.24) 1263.41,2971.24 v2(1263.41,3104.19) ; U4.0@2128.17,1806.92 ccw(c2081.15,1853.94) 2147.64,1853.94 v1(2148.27,1973.12) ; P5.1@2585.09,83.11 J3.1@2585.09,367.45 ; v2(3228.7,130.24) 3548.2,130.24 cw(c3548.2,30.24) 3618.91,100.95 v2(3646.03,73.83)
  Layer 2 w20: v2(553.86,1195.84) 580.02,1195.84 ccw(c580.02,1270.97) 633.14,1217.85 649.45,1234.16 cw(c699.2,1184.4) 699.2,1254.77 785.23,1254.77 cw(c785.23,1195.06) 827.44,1237.28 cw(c788.35,1198.19) 843.64,1198.19 843.64,1118.18 cw(c794.99,1118.18) 829.39,1083.78 ccw(c889.06,1024.11) 804.67,1024.11 v2(804.67,964.49) ; v2(899.56,695.14) 1130.56,695.14 cw(c1130.56,608.72) v2(1191.67,669.83) ; P4.2@1108.22,383.63 1146.73,383.63 ; 1162.38,383.63 1268.11,383.63 cw(c1268.11,283.63) 1338.82,354.34 1373.31,319.85 ccw(c1444.02,390.56) 1444.02,290.56 2096.33,290.56 ccw(c2096.33,390.56) 2167.04,319.85 2186.71,339.52 ccw(c2116,410.23) 2216,410.23 J5.0@2216,469.17 ; v2(1463.2,980.83) ccw(c1461.3,982.73) 1463.99,982.73 v2(1463.99,1255.98) ; J5.0@1709.86,469.17 2099.63,469.17 ; J5.7@1968.52,606.96 1968.52,642.22 cw(c2013.47,642.22) 1981.68,674 cw(c2042.58,613.1) v1(2042.58,699.23) 2147.81,699.23 cw(c2147.81,613.1) 2208.71,674 cw(c2164.13,629.42) 2227.18,629.42 J5.0@2227.18,469.17 ; J5.4@2106.31,547.91 2106.31,485.3 cw(c2083.5,485.3) 2099.63,469.17 ; v2(2485.62,2329.83) 2503.74,2311.71 2503.74,2125.58 v2(2503.42,2125.25) ; v2(2758.4,2708.06) 3378.06,2708.06 cw(c3378.06,2616.28) v2@3442.95,2681.18 ; v2(3395.43,841.75) 3373.7,841.75 3318.17,786.21 ccw(c3318.17,686.21) 3247.46,756.93 3158.83,668.3 cw(c3088.12,739.01) 3088.12,639.01 v2(3032.56,639.01) 2957.9,639.01 ccw(c2957.9,156.96) 2617.03,497.82 2585.09,465.88 J3.1@2585.09,367.45 2328.9,367.45 J5.0@2227.18,469.17 ; 2099.63,469.17 J5.0@2216,469.17 ; J5.0@2216,469.17 J5.0@2227.18,469.17
  Layer 2 w30: 1146.73,383.63 ccw(c1146.73,404.85) 1161.74,389.84 1162.38,390.48 ccw(c1091.67,461.19) 1191.67,461.19 v2(1191.67,669.83) ; J6.4@3413.66,2478.72 3413.66,2610.46 cw(c3513.66,2610.46) v2@3442.95,2681.18
  Bottom Layer w6: C23.2@2109.81,1936.13 2145.77,1972.08 cw(c2148.27,1969.58) v1(2148.27,1973.12) 2219.29,1973.12 ccw(c2219.29,2073.12) 2290,2002.41 2324.64,2037.05 cw(c2395.35,1966.34) v1(2395.35,2066.34) v1@2395.77,2066.34 ; v2(3312.09,2910.53) ccw(c3338.83,2937.27) 3338.83,2899.46 C61.2@3398.87,2899.46
  Bottom Layer w10: v4@3540.78,3008.83 cw(c3507.34,2975.39) 3554.63,2975.39 3554.63,2953.01 ccw(c3580.18,2953.01) 3562.11,2934.95 3567.39,2929.67 ccw(c3594.4,2956.68) 3594.4,2918.48 3622.75,2918.48 ccw(c3622.75,2949.14) 3644.43,2927.46 ccw(c3627.68,2944.22) 3651.37,2944.22 C68.2@3651.37,2956.7
  Bottom Layer w20: v2(386.25,1331.6) 398.8,1331.6 520.9,1209.5 ccw(c553.86,1242.45) v2(553.86,1195.84) 641.82,1283.81 ccw(c571.11,1354.52) 671.11,1354.52 v2(671.11,1403.94) ; v2(804.67,964.49) 870.27,898.89 cw(c799.56,828.18) 899.56,828.18 v2(899.56,695.14) ; v2(1259.73,2962.37) ccw(c1311.51,2962.37) 1274.9,2925.76 R24.1@1291.18,2909.48 R23.1@1291.18,2804.76 1291.18,2757.51 ccw(c1347.48,2757.51) 1307.67,2717.7 ccw(c1337.11,2747.14) 1337.11,2705.51 FMI1.1@1414.36,2705.51 ; v2(1463.99,1255.98) 1462.47,1257.5 cw(c1533.18,1328.21) 1433.18,1328.21 1433.18,1340.48 1506.79,1414.09 cw(c1528.1,1392.78) v2(1528.1,1422.92) ; v2(1595.59,2179.32) 1623.64,2151.27 ccw(c1694.35,2221.99) 1694.35,2121.99 v2(1702.67,2121.99) ; v2(1642.15,2977.88) 1755.35,2977.88 cw(c1755.35,2954.18) 1772.11,2970.94 1784.19,2958.86 cw(c1761.88,2936.54) 1793.44,2936.54 1793.44,2918.2 cw(c1734.71,2918.2) 1776.24,2876.68 1771.81,2872.25 ccw(c1842.52,2801.54) 1742.52,2801.54 1742.52,2592.64 ccw(c1842.52,2592.64) v2@1771.81,2521.93 ; v2(1774.36,2313.13) ccw(c1771.93,2315.56) 1775.37,2315.56 C16.1@1775.37,2335.2 C42.1@1775.37,2401.28 C43.1@1775.37,2467.37 v2@1775.37,2518.37 ; 1898.46,2649.88 cw(c1898.46,2575.51) 1951.04,2628.1 cw(c1916.64,2593.69) 1965.29,2593.69 C41.1@1965.29,2582.46 C15.1@1965.29,2515.77 1969.77,2511.29 cw(c1930.45,2471.97) U5.49@1986.05,2471.97 ; C52.1@2085.63,2330.59 2085.63,2362.88 cw(c2095.15,2362.88) U5.49@2088.42,2369.61 ; C56.1@2393.75,2328.02 C55.1@2393.75,2390.13 ; v2(2422.49,2513.21) ccw(c2419.76,2510.48) 2419.76,2514.34 2393.75,2514.34 C55.1@2393.75,2390.13 ; v2(2485.8,2402.78) cw(c2455.26,2433.32) 2455.26,2390.13 C55.1@2393.75,2390.13 ; C45.1@2618.17,2705.28 2639.71,2705.28 ccw(c2639.71,2707.8) 2641.49,2706.02 2644.06,2708.6 v2(2648.19,2708.6) 2757.1,2708.6 cw(c2757.1,2706.75) v2(2758.4,2708.06) ; C45.1@2630.54,2695.07 C44.1@2727.47,2598.15 ; v2(3301.61,3075.17) cw(c3303.31,3073.47) 3303.31,3075.88 C60.2@3344.38,3075.88 ; v2(3312.09,2910.53) 3312.09,2947.39 cw(c3369.52,2947.39) 3328.91,2988 cw(c3359.88,2957.03) 3359.88,3000.83 R79.2@3398.87,3000.83 ; v2(3395.43,841.75) 3419.26,841.75 3423.5,845.98 ccw(c3323.5,845.98) 3394.21,916.7 3276.25,1034.66 ccw(c3234.85,1125.68) 3305.56,1054.97 3457.09,1206.5 cw(c3527.8,1135.79) 3527.8,1235.79 P6.2@3612.66,1235.79 ; C63.2@3454.09,2768.39 3524.91,2768.39 ccw(c3524.91,2770.11) C62.2@3526.13,2768.89 ; C67.2@3519.99,3021.86 cw(c3519.99,3003.12) 3533.23,3016.38 v4@3540.78,3008.83 ; C64.2@3607.22,3090.21 cw(c3595.99,3078.98) 3611.87,3078.98 C69.2@3611.87,3038.36 3633.96,3038.36 cw(c3633.96,3018.56) 3647.96,3032.56 cw(c3639.74,3024.34) 3651.37,3024.34 C68.2@3651.37,2956.7
  Bottom Layer w30: v2(299.87,937.08) 299.87,815.46 ccw(c399.87,815.46) 329.16,744.75 369.79,704.11 ; v2(1008.01,3075.71) cw(c1016.77,3066.96) 1016.77,3079.34 C21.2@1056.01,3079.34 ; v2@1017.34,3238.71 C19.2@1053.53,3238.71 ; v2(1231.99,3468.63) cw(c1234.05,3466.57) 1234.05,3469.48 R6.2@1278.35,3469.48 1278.35,3512.14 cw(c1300.7,3512.14) 1284.9,3527.94 cw(c1336.18,3476.66) v1(1336.18,3549.19) 1364.55,3549.19 cw(c1364.55,3534.39) 1375.01,3544.86 FMI1.9@1414.36,3505.51 ; v2@1278.35,3238.7 1278.35,3208.6 ccw(c1287.94,3208.6) C20.2@1281.16,3201.83 ; C34.2@1643.35,1694.32 1625.01,1694.32 cw(c1625.01,1695.96) v2(1623.84,1694.8) cw(c1676.5,1747.45) 1602.03,1747.45 1602.03,1787.43 cw(c1632.78,1787.43) 1611.04,1809.18 1621.09,1819.22 cw(c1660.22,1780.09) C35.1@1660.22,1835.43 ; C35.1@1660.23,1835.45 C32.2@1727.98,1835.45 1747.56,1835.45 cw(c1747.56,1816.62) 1760.87,1829.93 ccw(c1809.83,1878.89) 1809.83,1809.65 1842.69,1809.65 cw(c1842.69,1792.81) 1854.6,1804.72 cw(c1818.33,1768.45) 1869.62,1768.45 C38.1@1869.62,1755.37 ; C36.1@1869.62,1691.49 C38.1@1869.62,1755.37 ; C46.1@1935.23,1573.66 C49.1@1999.49,1573.66 1999.49,1611.47 ccw(c1977.73,1611.47) U4.0@1993.12,1626.86 ; U4.0@1948.1,1761.91 1921.98,1761.91 1912.35,1752.28 1887.49,1752.28 1887.41,1752.37 1872.62,1752.37 C38.1@1869.62,1755.37 ; U4.0@2128.17,1626.86 ccw(c2140.38,1614.65) 2123.11,1614.65 C50.1@2123.11,1563.26 2203.88,1563.26 cw(c2203.88,1526.68) 2229.75,1552.55 cw(c2197.32,1520.12) 2243.18,1520.12 C51.1@2243.18,1499.94 ; v2(3446.04,2684.26) ccw(c3436.12,2694.18) 3450.15,2694.18 3450.15,2753.79 ; v2(3792.01,1910.66) ccw(c3749.46,1953.21) 3809.64,1953.21 R88.1@3809.64,1967.68
  Bottom Layer w50: v2(118.37,586.36) 400.91,586.36 cw(c400.91,582.7) 403.49,585.29 ; 374.23,688.2 cw(c303.57,617.54) 403.49,617.54 403.49,585.29 ; v2(403.49,473.09) 403.49,585.29
  other v1: 1626.27,292.03 1670.75,292.03 1715.24,292.03 1759.72,292.03 1804.2,292.03 1848.68,292.03 1893.16,292.03 1948.22,304.86 1588.23,306.04 2102.52,323.71 1555.56,333.55 1978.47,332.81 2061.94,357.67 1649.4,358.67 1693.74,358.67 1738.08,358.67 1782.42,358.67 1826.76,358.67 1871.11,358.67 1999.91,365.74 1531.49,369.95 1904.79,371.38 2132.34,375.06 2054.48,391.63 1615.92,391.71 2103.35,393.28 1927.15,396.28 2011.39,397.12 1518.9,409.52 1874.78,411.29 1594.49,421.58 1932.57,427.9 1818.89,432.37 2010.88,432.77 2068.56,435.52 2105.01,441.32 1518.9,449.96 1859.45,457.28 1587.01,464.21 1931.82,466.36 2015.53,469.46 1518.9,490.39 1935.44,497.36 1587.01,499.13 2017.08,500.46 2078.5,504.27 1518.9,530.82 1587.01,534.06 1672.46,555.52 1641.1,565.97 1587.01,568.99 1518.9,571.26 578.71,583.31 550.22,588.73 616.25,589.64 2185.44,595.08 2360.73,598.61 2405.67,601.33 671.67,610 718.12,610.71 996.77,610.71 951.04,612.86 896.74,615 827.43,618.57 769.56,622.14 2180.25,634.68 1518.9,651.97 1590.3,651.97 1768.21,653.47 1656.5,656.22 1990.73,657.31 1892.03,658.43 1715.39,662.83 2027.5,665.33 2121.7,664.86 2362.09,681.68 1813.05,688.65 1518.9,691.63 1590.3,691.63 1886.53,704.65 2121.7,707.75 1942.04,710.76 2412.48,723.89 1673.31,728.59 1518.9,731.29 1590.3,731.29 1814.69,736.29 2053.63,745.04 2121.7,745.04 1884.88,751.43 1737.43,753.34 1955.14,763.15 1518.9,770.94 1590.3,770.94 2329.41,782.45 1816.41,783.54 2053.63,785.45 2121.7,785.45 1906.75,791.12 2234.09,794.7 1518.9,810.6 1590.3,810.6 1934.45,819.8 1732.56,823.21 1833.56,823.76 2053.63,825.86 2121.7,825.86 2416.56,827.38 2198.68,838.28 1644.82,845.96 1959.51,846.84 1518.9,850.26 1590.3,850.26 1863.97,852.92 2053.63,866.27 2121.7,866.27 1708.18,868.7 1981.93,872.56 1815.42,880.08 1894.55,882.78 1518.9,889.92 1590.3,889.92 2300.81,896.83 2053.63,906.68 2121.7,906.68 1998.74,908.83 1922.91,913.44 2238.18,914.53 1670.81,917.45 1856.04,923.95 1520.47,926.91 2166,930.87 1735.8,932.07 1611.59,933.53 1997.59,947.33 2053.63,947.09 2121.7,947.09 1934.84,952.54 1530.69,955.34 1807.3,958.07 1640.1,966.92 2411.12,974.45 1557.52,985.8 1997.59,986.06 2053.63,987.5 2121.7,987.5 2351.2,988.07 1934.84,990.17 1673.35,1000.03 2227.28,1005.77 1742.3,1013.31 1587.56,1015.28 1854.42,1019.81 1997.59,1024.78 1934.84,1027.81 2053.63,1027.91 2121.7,1027.91 1706.61,1033.14 1794.74,1039.11 2182.34,1039.81 1617.6,1044.75 1997.59,1063.51 1934.84,1065.44 1739.86,1066.25 2053.63,1068.32 2121.7,1068.32 1647.64,1074.23 2311.71,1073.86 1859.29,1075.05 2396.14,1092.92 1773.12,1099.36 1997.59,1102.23 1934.84,1103.07 1677.68,1103.7 2053.63,1108.73 2121.7,1108.73 2201.41,1110.62 1806.37,1132.47 1707.72,1133.18 1934.84,1140.71 1997.59,1140.95 2053.63,1149.14 2121.7,1149.14 1737.76,1162.65 1839.63,1165.58 2185.07,1171.9 1934.84,1178.34 2235.66,1177.96 1997.59,1179.68 2334.86,1184.16 2051.59,1189.55 2121.7,1189.55 1767.8,1192.13 1872.89,1198.69 2280.39,1199.14 1934.84,1215.98 1997.59,1218.4 1797.84,1221.6 2053.63,1229.96 2121.7,1229.96 1896.26,1240.96 1827.88,1251.07 1934.84,1253.61 1997.59,1257.13 2219.11,1257.69 2053.63,1270.37 2121.7,1270.37 1902.75,1281.4 1840.26,1287.64 1934.84,1291.24 1997.59,1295.85 2053.63,1310.78 2121.7,1310.78 1905.41,1315.36 1840.26,1319.32 1934.84,1328.88 1997.59,1334.58 2171.45,1348.93 1840.26,1351.01 2053.63,1351.19 2121.7,1351.19 1901.42,1354.65 2011.89,1362.77 1840.26,1382.7 2021.66,1398.96 2103.97,1403.92 1898.49,1409.32 1840.26,1414.39 1389.38,1420.92 1900.65,1441.24 1840.26,1446.08 1924.54,1451.04 2008.71,1454.22 1205.74,1469.08 1290.5,1469.08 1467.72,1471 1299.71,1511.56 1398.69,1512.18 1440.83,1513.38 1350.99,1515.76 1481.86,1523.5 1326.74,1543.59 1506.54,1556.34 1547.3,1561.96 1586.65,1580.57 1617.78,1599.17 1749.8,1602.75 1658.57,1604.54 1321.61,1618.61 1532.56,1636.59 1492.65,1643.17 1293.22,1646.12 1571.16,1652.82 1347.48,1657.65 1456.69,1660.72 1624.23,1660.72 1402.31,1662.47 1185.83,1687.4 1289.85,1687.4 826.04,1885.4 767.51,1890.23 844.3,1905.27 1008.59,1957.1 1063.75,1960.56 839.27,1962.56 895.39,1962.56 951.51,1962.56 1119.87,1962.56 1175.99,1962.56 626.27,1963.81 1235.94,1964.93 1300.73,2000.64 1425.61,2006.26 2927.17,2009.34 2765.29,2013.99 2543.8,2015.5 606.93,2018.11 1345.63,2022.51 2747.67,2032.08 2577.53,2037.99 582.75,2039.17 2940.28,2038.98 874.24,2056.18 914.41,2057.12 954.58,2057.43 994.75,2057.12 1155.43,2058.15 1034.92,2059.01 1075.09,2059.95 1115.26,2059.95 1195.6,2060.42 1387.64,2059.93 2601.97,2060.96 1233.55,2068.39 1275.76,2088.39 2835.82,2090 550.77,2095.33 1424.48,2103.09 1309.98,2115.47 2841.65,2119.15 1540.86,2127.74 1337.82,2143.92 545.31,2156.95 859.69,2167.53 903.04,2167.53 946.39,2167.53 989.74,2167.53 1033.09,2167.53 1076.44,2167.53 1119.79,2167.53 1163.14,2167.53 1206.5,2167.53 1472.83,2166.98 1365.66,2172.38 2820.46,2177.29 1261.21,2184.33 2946.97,2198.34 1393.49,2200.83 1507.36,2201.52 1289.81,2213.29 554.67,2215.45 2945.64,2227.55 1421.33,2229.29 581.19,2233.39 638.13,2238.07 1538.44,2238.93 905.45,2241.44 945.89,2241.44 986.33,2241.44 1026.77,2241.44 1067.2,2241.44 1107.64,2241.44 1148.08,2241.44 867.12,2242.51 1318.42,2242.24 1201.09,2254.48 1449.17,2257.74 1347.02,2271.2 1225,2275.56 1574.13,2280.95 1477.01,2286.2 2832.17,2288.29 1776.08,2288.91 1249.39,2298.81 1375.63,2300.16 1602.33,2303.97 2943.42,2307.89 1504.85,2314.65 2832.17,2319.78 1275.49,2323.77 1404.23,2329.11 1685.57,2331.31 1160.7,2335.56 869.68,2343.47 1532.69,2343.11 1121.76,2345.49 1200.89,2347.6 1299.88,2347.02 894.88,2356.31 979.86,2358.29 1432.83,2358.07 928.97,2358.78 1027.79,2358.78 1074.23,2360.76 1573.55,2367.86 1325.98,2371.98 1231.27,2373.7 1461.44,2387.03 2941.95,2391.87 1351.23,2396.08 1256.43,2400.41 1496.98,2406.34 1376.47,2420.18 1281.59,2427.12 2940.14,2430.37 1412.8,2448.91 1306.75,2453.84 1331.91,2480.55 1367.08,2501.02 1403.94,2510.58 1443.44,2510.58 1482.94,2510.58 1522.43,2510.58 1561.93,2510.58 1601.43,2510.58 1683.77,2513.1 1764.5,2543.05 2934.39,2569.15 2935.79,2609.14 3540.91,2616.92 3482.73,2618.58 3339.11,2623.84 3400.45,2626.06 2168.63,2637.09 2092.27,2641.64 2040.52,2645.74 3363.04,2661.37 2115.37,2662.7 3316.12,2668.88 2181.5,2672.09 2012.45,2682.87 2122.39,2697.2 3364.17,2702.46 3320.11,2704.58 2187.06,2711.3 2004.26,2719.71 3309.53,2739.12 2126.19,2740.18 1350.35,2747.03 2184.59,2748.04 2013.1,2752.62 3585.29,2759.08 3631.34,2767.5 3308.48,2770.49 1230.91,2774.63 1478.39,2775.66 2034.09,2776.44 2101.05,2779.66 2127.02,2779.18 2182.93,2782.05 3590.88,2786.14 3635.14,2812.4 1491.11,2817.92 1305.26,2847.46 1193.78,2851.42 2185.58,2853.23 2037.45,2857.27 2097.61,2859.73 1271.18,2862.45 1487.02,2870.63 2127.88,2882.26 2185.58,2898.38 2037.45,2901.13 2097.61,2904.13 2127.88,2924.09 2185.58,2943.54 2037.45,2944.98 2097.61,2948.54 2127.88,2965.92 2037.45,2988.83 2185.58,2988.7 1280.17,2993.58 2097.61,2992.94 1338.45,2993.92 2127.88,3007.75 2037.45,3032.69 2185.58,3033.85 2097.61,3037.35 2127.88,3049.58 2185.58,3079.01 2097.61,3081.75 2127.88,3091.42 2009.42,3106.21 2185.58,3124.16 2127.88,3133.25 1976.06,3138.23 2037.57,3152.91 2185.58,3169.32 1942.7,3170.26 2011.3,3185.59 2093.27,3200.79 1909.35,3202.29 1976.06,3220.83 2062.96,3227.94 1875.99,3234.31 2139.67,3236.64 1940.82,3256.71 2031.81,3259.32 2115.68,3261.42 1842.63,3266.34 1238.82,3276.11 1916.41,3283.21 2001.27,3286.2 2090.9,3290.41 1891.48,3305.41 1975.7,3316.51 2061.38,3317.04 1478.6,3323.02 1528.2,3323.02 1577.8,3323.02 1627.39,3323.02 1676.99,3323.02 1726.59,3323.02 1773.41,3323.16 1813.78,3372.79 1465.4,3386.86 1515.38,3386.86 1565.35,3386.86 1615.33,3386.86 1665.31,3386.86 1715.28,3386.86 1765.26,3386.86 1897.06,3391.79 1986.44,3396.05 1960.8,3423.16 1866.09,3428.4 1930.78,3454.92 1823.85,3470.64 1907.18,3484.06 1787.71,3504.43 1286.86,3507.45 1337.22,3514.7 1883.32,3517.27 1748.55,3524.53 1278.86,3547.79 1843.92,3551.48 1726.78,3560.81 1806.6,3584.14 1501.15,3584.7 1559.96,3584.7 1277.98,3585.72 1638.36,3585.78 1410.41,3587.24 1695.16,3586.73 1336.63,3590.13 1706.97,3734.61 1663.18,3734.74 1450.49,3741.08 1319.08,3745.3 1398.77,3745.3 1507.5,3744.86
  other v2: 316.87,52.62 362.05,56.23 307.23,104.3 1081.22,159.38 604.92,168.39 714.22,168.06 800.74,169.77 1035.32,181.8 930.96,185.19 572.88,213.93 3321.56,223.56 979.79,233.17 3373.55,263.48 534.93,274.65 53.38,289.83 3791.44,294.54 1029.99,299.32 3853.45,300.1 3404.18,310.83 2295.86,330.32 3688.7,351 3881.22,356.56 3729.43,371.37 542.79,378.41 3173.58,402.84 3506.3,413.87 766.33,416.88 637.41,423.12 984.32,439.08 3218.51,438.78 2477.52,452.34 3545.29,451.93 2566.86,467.24 2849,471.48 3273.81,485.09 1189.65,504.93 2395.07,518.73 2551.97,523.49 2801.52,542.71 1184.49,571.99 2503.16,588.01 3215.05,596.38 3275.88,598.46 2791.92,614.54 1054.3,615.46 1130.43,623.8 2478.34,626.89 2679.9,634.2 2759.96,694.25 2276.52,698.87 1470.74,712.68 2672.2,728.12 2733.79,743.51 1470.01,760.29 2177.83,767.85 1650.99,776.26 1999.06,798.34 1470.74,827.68 1785.92,839.82 2958.57,852.83 1471.12,901.93 295.8,906.32 2967.81,949.82 1767.38,976.31 2171.52,982.37 3157.21,1017.04 809,1023.34 3288.3,1034.09 1521.87,1044.61 2957.03,1057.59 1467.71,1067.59 3134.45,1075.15 3225.85,1076.66 1559.61,1086.19 885.53,1100.73 945.8,1106.56 3101.81,1111.96 1485.22,1120.65 3281.96,1129.26 3447.28,1128.76 3352.59,1131.77 1606.11,1133.78 1890.75,1135.9 3561.17,1140.17 3792.37,1147.96 918.12,1156.44 1052.93,1156.3 985.02,1163.96 2958.57,1173.06 1013.71,1208.91 927.58,1211.1 2455.12,1217.71 2186.24,1223.18 1501.76,1242.35 1553.87,1244.53 2408.93,1253.12 1598.02,1266.24 2929.32,1271.6 3260.84,1285.05 2557.34,1292.24 2796.68,1294.58 3348.17,1294.56 2663.71,1296.15 2175.72,1303.1 1519.85,1362.5 1430.83,1379.87 1348.33,1384.21 1261.48,1418.22 1341.51,1450.31 2234.78,1527.89 46.73,1647.54 116.09,1653.54 262.75,1777.59 3333.43,1879.25 3459.06,1886.64 3492.84,1928.86 3332.38,1940.48 401.59,2040.35 3376.71,2054.49 245.77,2059.7 2447.71,2065.76 3423.17,2085.11 2484.07,2095.16 219.64,2105.19 415.14,2105.19 223.51,2182.61 2482,2186 426.75,2200.03 2509.58,2249.1 2491.01,2266.49 2506.61,2317.32 1163.17,2448.14 1046.9,2468.26 505.71,2508.11 1091.65,2513.35 3865.13,2516.6 1773.32,2518.42 1188.42,2519.66 627.34,2523.45 1283.08,2530.18 1021.18,2561.25 3792.83,2582.51 3658.88,2596.33 356.54,2637.21 2962.8,2654.03 3688.65,2654.8 1280.18,2666.41 2651.96,2678.38 2775.71,2682.86 3786.45,2686.7 748.76,2695.2 1157.93,2705.08 423.69,2708.94 3883.2,2717.53 2667.76,2723.15 1100.55,2757.48 347.16,2767.59 2236.17,2769.36 695.35,2774.56 3878.95,2804.7 1076.85,2837.32 3305.36,2843.66 2877.47,2860.74 2917.43,2862.79 2765.19,2863.82 529,2870.71 2810.31,2880.28 434,2885.92 2248.42,2890.28 327.55,2895.13 2863.98,2905.89 2678.35,2936.86 2802.25,2956.75 2243.52,2962.18 2887.76,2983.33 605.3,3005.01 2242.7,3023.46 2663.29,3023.51 2725.48,3038.8 487.79,3040.11 2891.18,3051.78 360.52,3062.46 1486.91,3068.73 2752.14,3084.29 2348.71,3089.8 1732.04,3110.5 2942.43,3124.5 2330.32,3139.6 1525.94,3144.06 828.51,3156.66 1613.58,3198.15 1809.42,3202.94 2954.89,3203.45 845.99,3227.21 1507.45,3244.03 1667.68,3246.08 2915.42,3256.09 409.96,3259.87 1582.77,3263.2 885.47,3269.92 950.19,3275.1 2495.78,3285.81 522.89,3304.13 2498.53,3319.63 666.48,3319.76 3016.31,3320.76 2843.24,3349.45 3186.2,3357.56 3111.63,3358.7 2943.19,3364.26 1067.69,3387.83 1131.44,3406.78 701.81,3409.02 822.17,3418.84 929.86,3421.43 1717.12,3454.04 1151.25,3464.5 3869.29,3463.85 1547.29,3478.3 1646.76,3478.3 945.36,3496.38 2028.88,3502.56 3519.03,3514.96 3630.52,3516.6 1530.31,3519.54 1121.1,3526.53 2737.86,3531.33 1970.65,3534.1 2209.62,3540.17 2310.31,3546.23 2893.07,3549.81 2263,3559.58 2789.6,3559.67 3811.41,3583.24 3178.85,3623.72 2837.64,3629.88 3634.13,3637.5 3428.91,3668.07 2725.54,3690.24 2944.93,3691.77 3564.41,3702.56 3532.83,3782.22 3346.51,3784.03
  other v6: 176.95,1068.14
  other v11: 1296.83,1384.22
HSI_n: C31.1 U5.39 | length 1429.1
  Top Layer w6.07: C31.1@1587.65,3670.39 1590.52,3673.26 ccw(c1585.78,3678.01) 1592.49,3678.01 1592.49,3678.27 cw(c1598.56,3678.27) 1594.27,3682.56 cw(c1598.56,3678.27) 1598.56,3684.34 1625.41,3684.34 cw(c1625.41,3639.7) 1656.97,3671.27 2064.11,3264.13 2120.43,3207.81 cw(c2049.72,3137.1) 2149.72,3137.1 2149.72,2698.8 cw(c2049.72,2698.8) 2120.43,2628.09 2116.53,2624.18 ccw(c2169.24,2571.47) 2094.69,2571.47 2094.69,2563.07 cw(c2090.7,2563.07) 2093.52,2560.25 ccw(c2096.35,2557.42) 2092.35,2557.42 U5.39@2092.35,2538.9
